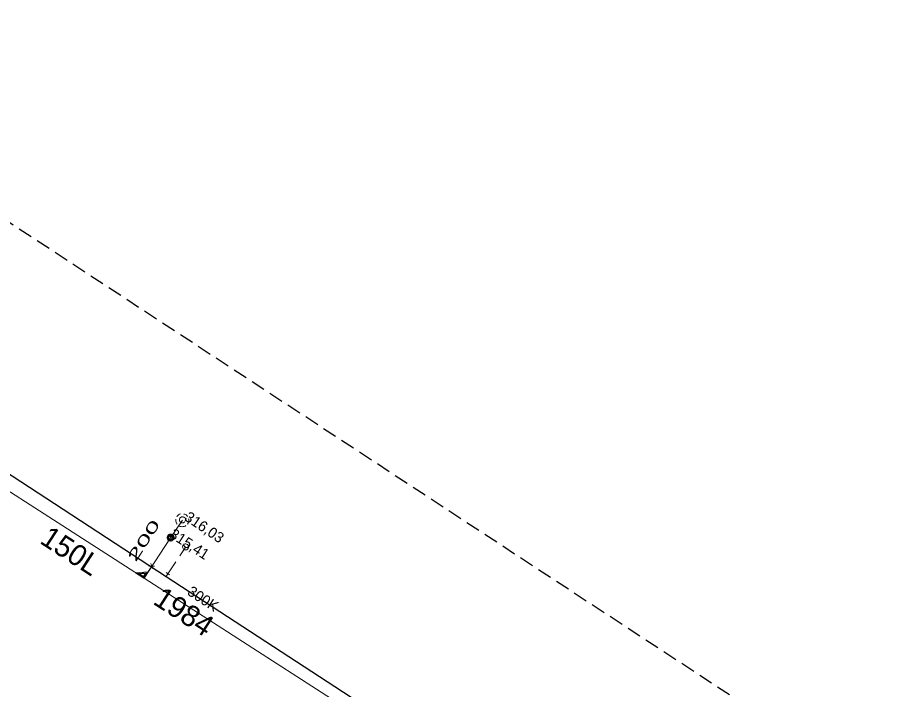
# Model space of a CAD drawing. Extents: x -742876 to -742577, y -1054710 to -1054452.
# Drawn here: x -742708.1 to -742642.5, y -1054502.9 to -1054452 of the extents above; entities that cross this region are included whole.
import ezdxf

# ---------------------------------------------------------------- set-up
doc = ezdxf.new("R2010")
doc.units = 0
doc.header["$LTSCALE"] = 0.36
doc.linetypes.add('MEDIUM_DASHED', pattern=[4.5, 3, -1.5])
for name, color, linetype, lineweight in [('1', 7, 'MEDIUM_DASHED', 25), ('18', 7, 'Continuous', 13), ('20', 7, 'Continuous', 13), ('49', 7, 'Continuous', 13), ('8', 7, 'Continuous', 13)]:
    doc.layers.add(name, color=color, linetype=linetype, lineweight=lineweight)

msp = doc.modelspace()

# ---------------------------------------------------------------- linework, layer by layer
at = {"layer": '1'}
msp.add_lwpolyline([(-742732.306, -1054452.031), (-742576.984, -1054553.898), (-742576.983, -1054553.899), (-742576.982, -1054553.901), (-742576.981, -1054553.903), (-742576.98, -1054553.905), (-742576.98, -1054553.907), (-742576.98, -1054553.909), (-742576.981, -1054553.91), (-742576.982, -1054553.912), (-742690.097, -1054710.32), (-742690.098, -1054710.321), (-742690.099, -1054710.322), (-742690.101, -1054710.323), (-742690.103, -1054710.324), (-742690.105, -1054710.324), (-742690.107, -1054710.324), (-742690.108, -1054710.323), (-742690.11, -1054710.322), (-742875.986, -1054593.411)], dxfattribs=at)
at = {"layer": '18'}
for p, q in [((-742697.683, -1054493.54), (-742698.127, -1054493.545)), ((-742697.961, -1054493.347), (-742697.825, -1054493.755))]:
    msp.add_line(p, q, dxfattribs=at)
for points in [[(-742695.732, -1054489.597), (-742695.803, -1054489.625), (-742695.87, -1054489.664), (-742695.93, -1054489.712), (-742695.981, -1054489.769), (-742696.005, -1054489.803)], [(-742695.191, -1054489.78), (-742695.241, -1054489.722), (-742695.299, -1054489.672), (-742695.364, -1054489.631), (-742695.435, -1054489.602), (-742695.484, -1054489.588)], [(-742696.077, -1054489.989), (-742696.083, -1054490.066), (-742696.078, -1054490.143), (-742696.061, -1054490.218), (-742696.032, -1054490.289), (-742695.992, -1054490.355), (-742695.976, -1054490.377)], [(-742695.819, -1054490.506), (-742695.749, -1054490.537), (-742695.674, -1054490.556), (-742695.598, -1054490.563), (-742695.521, -1054490.558), (-742695.446, -1054490.541), (-742695.374, -1054490.513), (-742695.314, -1054490.478)], [(-742695.196, -1054490.366), (-742695.155, -1054490.301), (-742695.124, -1054490.231), (-742695.105, -1054490.156), (-742695.097, -1054490.08), (-742695.102, -1054490.003), (-742695.108, -1054489.968)], [(-742697.896, -1054493.542), (-742698.489, -1054494.463), (-742699.136, -1054494.046), (-742698.176, -1054493.977)], [(-742698.282, -1054494.05), (-742698.507, -1054494.399), (-742698.983, -1054494.093), (-742698.281, -1054494.048)], [(-742698.367, -1054494.094), (-742698.525, -1054494.34), (-742698.838, -1054494.139), (-742698.366, -1054494.095)]]:
    msp.add_lwpolyline(points, dxfattribs=at)
for points in [[(-742695.348, -1054490.049), (-742695.354, -1054489.997), (-742695.372, -1054489.947), (-742695.4, -1054489.903), (-742695.438, -1054489.866), (-742695.483, -1054489.839), (-742695.533, -1054489.823), (-742695.585, -1054489.818), (-742695.637, -1054489.825), (-742695.686, -1054489.844), (-742695.73, -1054489.874), (-742695.765, -1054489.913), (-742695.791, -1054489.958), (-742695.806, -1054490.009), (-742695.809, -1054490.061), (-742695.801, -1054490.113), (-742695.78, -1054490.161), (-742695.75, -1054490.204), (-742695.71, -1054490.239), (-742695.664, -1054490.263), (-742695.613, -1054490.277), (-742695.561, -1054490.279), (-742695.509, -1054490.269), (-742695.461, -1054490.247), (-742695.419, -1054490.215), (-742695.386, -1054490.175), (-742695.362, -1054490.128), (-742695.35, -1054490.077)], [(-742696.205, -1054491.386), (-742696.211, -1054491.33), (-742696.228, -1054491.277), (-742696.257, -1054491.228), (-742696.295, -1054491.187), (-742696.341, -1054491.155), (-742696.393, -1054491.133), (-742696.448, -1054491.122), (-742696.504, -1054491.124), (-742696.559, -1054491.137), (-742696.61, -1054491.162), (-742696.654, -1054491.197), (-742696.69, -1054491.24), (-742696.715, -1054491.29), (-742696.73, -1054491.345), (-742696.733, -1054491.401), (-742696.724, -1054491.456), (-742696.703, -1054491.509), (-742696.672, -1054491.555), (-742696.632, -1054491.594), (-742696.584, -1054491.624), (-742696.531, -1054491.643), (-742696.475, -1054491.65), (-742696.419, -1054491.646), (-742696.365, -1054491.629), (-742696.316, -1054491.602), (-742696.274, -1054491.564), (-742696.241, -1054491.519), (-742696.218, -1054491.468), (-742696.206, -1054491.413)], [(-742696.264, -1054491.389), (-742696.27, -1054491.34), (-742696.288, -1054491.294), (-742696.316, -1054491.253), (-742696.353, -1054491.22), (-742696.397, -1054491.198), (-742696.445, -1054491.186), (-742696.494, -1054491.186), (-742696.542, -1054491.198), (-742696.586, -1054491.221), (-742696.623, -1054491.254), (-742696.651, -1054491.295), (-742696.668, -1054491.342), (-742696.674, -1054491.391), (-742696.667, -1054491.44), (-742696.649, -1054491.486), (-742696.621, -1054491.526), (-742696.584, -1054491.559), (-742696.54, -1054491.581), (-742696.491, -1054491.593), (-742696.442, -1054491.592), (-742696.394, -1054491.58), (-742696.351, -1054491.556), (-742696.314, -1054491.523), (-742696.286, -1054491.482), (-742696.27, -1054491.435)], [(-742696.323, -1054491.393), (-742696.329, -1054491.351), (-742696.346, -1054491.313), (-742696.374, -1054491.282), (-742696.409, -1054491.259), (-742696.449, -1054491.248), (-742696.491, -1054491.248), (-742696.531, -1054491.26), (-742696.566, -1054491.283), (-742696.593, -1054491.315), (-742696.61, -1054491.353), (-742696.615, -1054491.394), (-742696.609, -1054491.436), (-742696.591, -1054491.473), (-742696.563, -1054491.505), (-742696.527, -1054491.527), (-742696.487, -1054491.538), (-742696.445, -1054491.537), (-742696.405, -1054491.524), (-742696.371, -1054491.501), (-742696.344, -1054491.468), (-742696.328, -1054491.43)]]:
    msp.add_lwpolyline(points, close=True, dxfattribs=at)
at = {"layer": '20'}
msp.add_lwpolyline([(-742676.87, -1054508.37), (-742698.484, -1054494.465), (-742717.239, -1054482.399)], dxfattribs=at)
msp.add_lwpolyline([(-742676.87, -1054508.37), (-742698.484, -1054494.465), (-742717.239, -1054482.399)], dxfattribs=at)
at = {"layer": '49'}
for p, q in [((-742695.579, -1054490.06), (-742696.469, -1054491.399)), ((-742695.579, -1054490.06), (-742696.469, -1054491.399)), ((-742696.469, -1054491.399), (-742698.484, -1054494.465)), ((-742696.469, -1054491.399), (-742698.484, -1054494.465))]:
    msp.add_line(p, q, dxfattribs=at)
at = {"layer": '8'}
msp.add_line((-742696.55, -1054494.194), (-742696.804, -1054494.028), dxfattribs=at)
at = {"layer": '8', "lineweight": 25}
msp.add_lwpolyline([(-742715.62, -1054482.05), (-742696.811, -1054494.328), (-742670.64, -1054511.411), (-742668.59, -1054512.75)], dxfattribs=at)
at = {"layer": '8', "linetype": 'MEDIUM_DASHED'}
msp.add_lwpolyline([(-742696.811, -1054494.328), (-742696.671, -1054494.115), (-742695.333, -1054492.097)], dxfattribs=at)
at = {"layer": '8'}
msp.add_lwpolyline([(-742695.215, -1054491.896), (-742695.262, -1054491.873), (-742695.313, -1054491.861), (-742695.365, -1054491.86), (-742695.417, -1054491.872), (-742695.464, -1054491.894), (-742695.505, -1054491.927), (-742695.538, -1054491.968), (-742695.56, -1054492.016), (-742695.571, -1054492.067), (-742695.57, -1054492.12), (-742695.557, -1054492.171), (-742695.534, -1054492.217), (-742695.499, -1054492.258), (-742695.457, -1054492.289), (-742695.409, -1054492.311), (-742695.358, -1054492.319), (-742695.305, -1054492.318), (-742695.254, -1054492.303), (-742695.209, -1054492.278), (-742695.169, -1054492.243), (-742695.139, -1054492.201), (-742695.119, -1054492.152), (-742695.111, -1054492.099), (-742695.115, -1054492.047), (-742695.13, -1054491.997), (-742695.156, -1054491.951), (-742695.192, -1054491.913)], close=True, dxfattribs=at)

# ---------------------------------------------------------------- texts
at = {"layer": '1'}
for s, height, rotation, p in [('316,03', 0.8, 326, (-742695.49, -1054490.016)), ('150L', 1.6, 327, (-742706.447, -1054491.761)), ('315,41', 0.8, 327, (-742696.631, -1054491.316)), ('300K', 0.8, 327, (-742695.274, -1054495.662)), ('1984', 1.6, 327, (-742697.887, -1054496.355))]:
    msp.add_text(s, height=height, rotation=rotation, dxfattribs=at).set_placement(p)
at = {"layer": '1', "width": 1.95}
msp.add_text('200 ', height=0.8, rotation=57, dxfattribs=at).set_placement((-742699.118, -1054493.284))

doc.saveas('drawing.dxf')
